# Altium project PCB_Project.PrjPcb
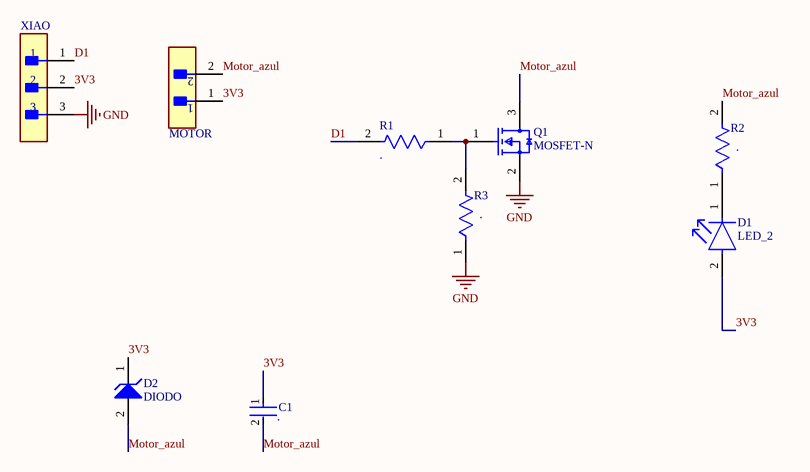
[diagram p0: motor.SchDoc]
1 sheet, 9 parts. Net scope: global (net labels, ports and power ports of the same name join across sheets).
Board file: motor.PcbDoc

## Sheet motor.SchDoc
size A4; SheetNumber: 1; SheetTotal: 1

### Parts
C1  .  [FP-C1206C-EB-MFG]
D1  LED_2  [FP-LTST-C150KSKT-MFG]
D2  DIODO  [ONSC-SOD-123-2-425-04_V]
MOTOR  M20-9990246  [FP-M20-9990246-MFG]  (value not drawn)
Q1  MOSFET-N  [FP-SOT23-MFG]
R1  .  [FP-AC1206-MFG]
R2  .  [FP-AC1206-MFG]
R3  .  [FP-AC1206-MFG]
XIAO  (no value)  [FP-PR20203VBNN-MFG]

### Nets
GND: Q1.2(S) R3.1 XIAO.3
3V3: C1.1 D1.2(A) D2.1(K) MOTOR.1 XIAO.2
D1: R1.2 XIAO.1
Motor_azul: C1.2 D2.2(A) MOTOR.2 Q1.3(D) R2.2
NetD1_1: D1.1(C) R2.1
NetQ1_1: Q1.1(G) R1.1 R3.2

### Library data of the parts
C1 = CMP-03020-023751-1: C1206 100 pF X8R 10.00% 50 V; Manufacturer: KEMET; Manufacturer Part Number: C1206C101K5HACTU; Capacitance: 100 pF; Temperature Coefficient: 15%; Voltage Rating: 50 V; Tolerance: 0.1; Automotive Grade: Grade 0; Value: 100 pF; Material: Ceramic
D1 = CMP-2000-06618-2: LED YELLOW CLEAR 1206 SMD; Power Rating: 75mW; Wavelength: 588nm; Forward Current: 30mA; Test Current: 20mA; Viewing Angle: 130°; Forward Voltage: 2.4V; Luminous Intensity: 60mcd; Lens Style: Diffused; Number of Elements: 1; Reverse Voltage: 5V; Lens Color: Colorless; Dominant Wavelength: 587nm
D2 = CMP-1060-00449-1: Zener Voltage Regulator, 500 mW, 2-Pin SOD-123, Pb-Free, Tape and Reel; Manufacturer: On Semiconductor; PartNumber: MMSZ5249BT1G; P Max (W): 0.5; VZ Typ (V): 19
MOTOR = CMP-15831-000009-1: CONN HEADER VERT 2POS 2.54MM; Manufacturer: Harwin; Conn Gender: Male; Conn Orientation: Vertical; Number Of Contacts: 2; Current Rating: 3A
Q1 = CMP-2000-04929-2: MOSFET N-CH 60V 115MA SOT23-3; Turn-On Delay Time: 7ns; Turn-Off Delay Time: 11ns; Drain to Source Resistance: 7.5R; Rise Time: 3ns; Drain to Source Breakdown Voltage: 70V; Input Capacitance: 50pF; Number of Elements: 1; Power Dissipation: 540mW; Max Power Dissipation: 300mW; Fall Time: 5.6ns; Gate to Source Voltage (Vgs): 20V; Threshold Voltage: 2.5V; Element Configuration: Single
R1-R3 = CMP-03412-032679-1: RES SMD 2.21K OHM 1% 1/4W 1206; Manufacturer: Yageo; Manufacturer Part Number: AC1206FR-072K21L; Automotive Grade: Grade 0; Voltage Rating: 200V; Tolerance: 0.01; Value: 2.21KΩ; Power Rating: 0.25W
XIAO = CMP-77940-000002-1: CONN HEADER VERT 3POS 2.54MM; Manufacturer Part Number: PR20203VBNN; Manufacturer: Metz Connect; Conn Orientation: Straight; Current Rating: 3A; Number Of Contacts: 3; Conn Gender: Male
